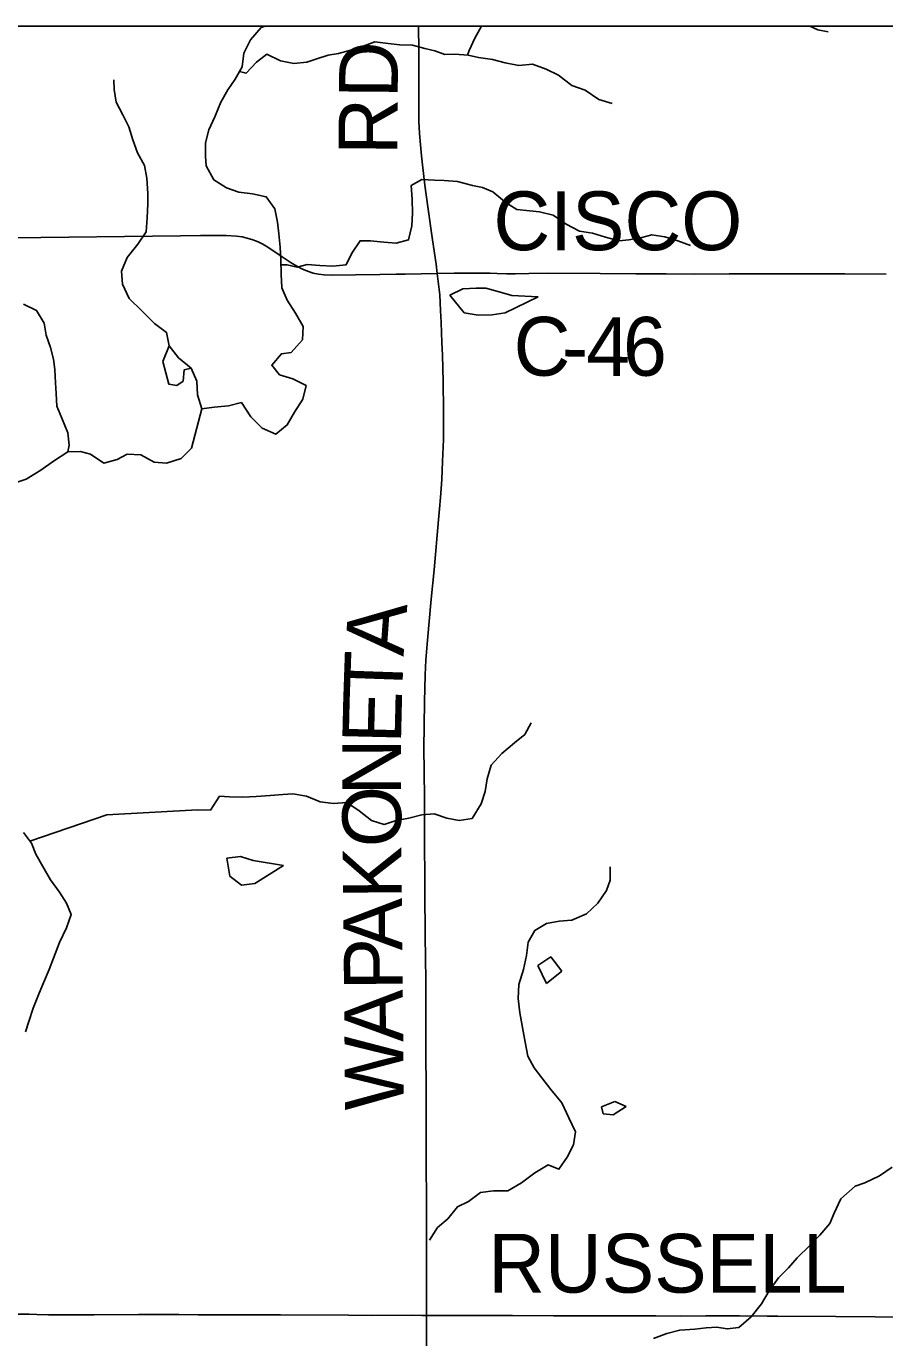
# Model space of a CAD drawing. Extents: x -87 to 2145, y -2128 to 440.
# Drawn here: x 177.65 to 199.56, y -858.65 to -825.19 of the extents above; entities that cross this region are included whole.
import ezdxf

# ---------------------------------------------------------------- set-up
doc = ezdxf.new("R2010")
doc.units = 0
for name, color, linetype in [('GM_X_County_Road', 7, 'Continuous'), ('GM_X_County_Road_Text', 7, 'Continuous'), ('GM_X_Minor_Lake', 7, 'Continuous'), ('GM_X_Minor_River', 7, 'Continuous'), ('GM_X_Township_Road', 7, 'Continuous'), ('SC_Scratch1', 7, 'Continuous')]:
    doc.layers.add(name, color=color, linetype=linetype)

msp = doc.modelspace()

# ---------------------------------------------------------------- linework, layer by layer
at = {"layer": 'GM_X_County_Road'}
for points in [[(188.144, -831.499), (188.12, -831.255), (188.026, -830.639), (187.901, -829.795), (187.826, -829.243), (187.765, -828.722), (187.741, -828.494), (187.714, -828.217), (187.69, -827.924), (187.675, -827.614), (187.673, -827.434), (187.675, -827.106), (187.675, -826.663), (187.675, -826.09), (187.676, -825.664), (187.67, -825.335), (187.668, -825.188)], [(187.869, -858.08), (187.868, -857.384), (187.866, -856.366), (187.867, -855.398), (187.859, -853.971), (187.862, -852.873), (187.859, -852.134), (187.854, -851.527), (187.852, -850.674), (187.85, -849.559), (187.844, -848.935), (187.839, -848.427), (187.83, -847.229), (187.827, -846.786), (187.823, -846.18), (187.819, -845.491), (187.815, -844.9), (187.807, -844.178), (187.805, -843.621), (187.82, -842.424), (187.837, -841.735), (187.854, -841.359), (187.892, -840.853), (187.993, -839.808), (188.062, -839.056), (188.18, -837.782), (188.205, -837.504), (188.228, -837.21), (188.258, -836.751), (188.281, -836.292), (188.301, -835.734), (188.305, -835.307), (188.304, -834.815), (188.296, -834.421), (188.292, -834.257), (188.275, -833.585), (188.264, -833.257), (188.244, -832.75), (188.229, -832.438), (188.206, -832.044), (188.144, -831.499)], [(188.144, -831.499), (188.577, -831.489), (189.495, -831.489), (189.674, -831.496), (189.92, -831.503), (190.051, -831.504), (190.133, -831.502), (190.478, -831.494), (190.953, -831.49), (192.298, -831.495), (193.216, -831.505), (193.987, -831.505), (194.709, -831.51), (195.595, -831.505), (196.07, -831.507), (196.694, -831.506), (197.186, -831.502), (198.548, -831.507), (199.598, -831.511)], [(187.88, -859.664), (187.871, -858.515), (187.869, -858.269), (187.869, -858.08)], [(187.869, -858.08), (188.72, -858.087), (190.065, -858.086), (191.115, -858.089), (191.919, -858.088), (192.526, -858.09), (193.001, -858.091), (193.723, -858.093), (194.362, -858.096), (195.002, -858.092), (195.856, -858.093), (196.561, -858.098), (196.84, -858.1), (198.316, -858.112), (199.316, -858.115), (200.596, -858.128)]]:
    msp.add_lwpolyline(points, dxfattribs=at)
at = {"layer": 'GM_X_Minor_Lake'}
for p, q in [((182.776, -846.417), (182.848, -846.87)), ((190.707, -849.157), (190.93, -849.613)), ((192.965, -852.749), (192.676, -852.623)), ((192.333, -852.756), (192.382, -852.94)), ((192.382, -852.94), (192.63, -852.962))]:
    msp.add_line(p, q, dxfattribs=at)
for points in [[(190.722, -832.091), (190.046, -832.057), (189.727, -831.961), (189.387, -831.873), (189.136, -831.868), (188.795, -831.891), (188.468, -832.046)], [(188.468, -832.046), (188.835, -832.503), (189.185, -832.56), (189.547, -832.548), (189.878, -832.505), (190.722, -832.091)], [(181.141, -833.742), (181.291, -834.317), (181.501, -834.351), (181.663, -834.244), (181.688, -833.953), (181.864, -833.914), (181.543, -833.649), (181.301, -833.342)], [(181.301, -833.342), (181.141, -833.742)], [(184.217, -846.598), (183.447, -846.472), (183.127, -846.375), (182.776, -846.417)], [(182.848, -846.87), (183.145, -847.106), (183.487, -847.063), (184.217, -846.598)], [(191.322, -849.297), (191.042, -848.934), (190.707, -849.157)], [(190.93, -849.613), (191.322, -849.297)], [(192.676, -852.623), (192.333, -852.756)], [(192.63, -852.962), (192.965, -852.749)]]:
    msp.add_lwpolyline(points, dxfattribs=at)
at = {"layer": 'GM_X_Minor_River'}
for points in [[(182.14, -834.948), (182.453, -834.91), (182.815, -834.876), (183.147, -834.791), (183.384, -835.156), (183.672, -835.441), (184.021, -835.597), (184.315, -835.361), (184.5, -835.033), (184.714, -834.706), (184.799, -834.357), (184.46, -834.181), (184.119, -834.085), (183.921, -833.832), (184.166, -833.545), (184.417, -833.509), (184.702, -833.193), (184.726, -832.853), (184.529, -832.509), (184.312, -832.175), (184.175, -831.862), (184.159, -831.511), (184.153, -831.15), (184.137, -830.829), (184.101, -830.488), (184.064, -830.187), (183.998, -829.845), (183.781, -829.541), (183.43, -829.465), (183.079, -829.419), (182.769, -829.314), (182.44, -829.108), (182.244, -828.754), (182.227, -828.504), (182.231, -828.163), (182.315, -827.834), (182.469, -827.496), (182.624, -827.128), (182.799, -826.81), (182.983, -826.543), (183.167, -826.225), (183.211, -825.875), (183.376, -825.537), (183.651, -825.221), (183.749, -825.188)], [(188.914, -825.927), (188.955, -825.809), (189.1, -825.49), (189.27, -825.188)], [(197.649, -825.188), (197.858, -825.283), (198.118, -825.327)], [(183.097, -826.346), (183.266, -826.387), (183.53, -826.101), (183.793, -825.905), (184.143, -826.071), (184.483, -826.136), (184.815, -826.102), (185.067, -826.016), (185.359, -825.93), (185.621, -825.884), (185.873, -825.818), (186.185, -825.723), (186.548, -825.589), (186.889, -825.625), (187.19, -825.66), (187.511, -825.675), (187.831, -825.76), (188.082, -825.814), (188.342, -825.909), (188.593, -825.903), (188.934, -825.928), (189.194, -825.983), (189.555, -826.039), (189.875, -826.124), (190.226, -826.19), (190.578, -826.156), (190.928, -826.281), (191.237, -826.437), (191.575, -826.703), (191.915, -826.818), (192.264, -827.055), (192.604, -827.16)], [(181.301, -833.342), (181.236, -833), (180.93, -832.774), (180.614, -832.457), (180.278, -832.131), (180.114, -831.766), (180.089, -831.435), (180.234, -831.086), (180.499, -830.749), (180.714, -830.431), (180.74, -830.08), (180.755, -829.719), (180.759, -829.458), (180.735, -829.066), (180.67, -828.743), (180.494, -828.419), (180.379, -828.086), (180.274, -827.753), (180.118, -827.449), (179.953, -827.125), (179.898, -826.803), (179.892, -826.552)], [(184.156, -831.28), (184.313, -831.273), (184.573, -831.337), (184.825, -831.271), (185.146, -831.296), (185.477, -831.312), (185.819, -831.277), (185.963, -830.979), (186.177, -830.662), (186.438, -830.666), (186.779, -830.702), (187.1, -830.727), (187.412, -830.642), (187.497, -830.283), (187.511, -829.962), (187.505, -829.602), (187.479, -829.251), (187.752, -829.095), (188.073, -829.12), (188.324, -829.124), (188.665, -829.15), (189.045, -829.256), (189.296, -829.3), (189.566, -829.415), (189.904, -829.691), (190.173, -829.866), (190.504, -829.901), (190.754, -829.925), (191.105, -830.011), (191.433, -830.237), (191.773, -830.413), (192.103, -830.468), (192.434, -830.574), (192.784, -830.66), (193.035, -830.634), (193.367, -830.579), (193.619, -830.513), (193.95, -830.558), (194.28, -830.664), (194.61, -830.779)], [(178.718, -836.051), (178.751, -835.881), (178.716, -835.559), (178.561, -835.185), (178.435, -834.882), (178.42, -834.56), (178.404, -834.289), (178.389, -833.947), (178.353, -833.686), (178.277, -833.383), (178.162, -833.07), (178.116, -832.768), (177.921, -832.443), (177.583, -832.277)], [(182.14, -834.948), (182.024, -834.589), (182.009, -834.248), (181.864, -833.914)], [(178.718, -836.051), (179.039, -836.037), (179.298, -836.111), (179.635, -836.338), (179.977, -836.243), (180.229, -836.106), (180.579, -836.122), (180.917, -836.308), (181.237, -836.334), (181.609, -836.219), (181.873, -835.953), (182.14, -834.948)], [(177.395, -836.833), (177.657, -836.747), (178.031, -836.512), (178.354, -836.286), (178.718, -836.051)], [(182.022, -845.184), (182.354, -845.19), (182.589, -844.833), (182.84, -844.847), (183.181, -844.862), (183.522, -844.838), (183.884, -844.814), (184.206, -844.789), (184.457, -844.773), (184.808, -844.829), (185.157, -844.975), (185.498, -845.02), (185.84, -844.996), (186.149, -845.211), (186.467, -845.457), (186.787, -845.552), (187.1, -845.457), (187.422, -845.392), (187.754, -845.308), (188.065, -845.283), (188.385, -845.398), (188.706, -845.453), (189.038, -845.399), (189.263, -845.032), (189.367, -844.713), (189.421, -844.393), (189.516, -844.044), (189.79, -843.748), (190.115, -843.472), (190.378, -843.256), (190.542, -842.958)], [(182.022, -845.184), (179.71, -845.309), (177.749, -845.978)], [(177.636, -850.844), (177.72, -850.585), (177.835, -850.245), (177.981, -849.856), (178.095, -849.597), (178.24, -849.258), (178.355, -848.969), (178.501, -848.57), (178.687, -848.191), (178.802, -847.852), (178.686, -847.559), (178.5, -847.285), (178.275, -846.97), (178.08, -846.625), (177.904, -846.311), (177.788, -846.028), (177.582, -845.763)], [(187.946, -856.159), (188.151, -855.842), (188.414, -855.616), (188.659, -855.31), (188.942, -855.174), (189.246, -854.949), (189.578, -854.904), (189.949, -854.9), (190.293, -854.695), (190.638, -854.441), (190.971, -854.236), (191.251, -854.35), (191.456, -854.043), (191.62, -853.725), (191.674, -853.396), (191.498, -853.042), (191.322, -852.659), (191.045, -852.314), (190.817, -852.02), (190.619, -851.766), (190.452, -851.463), (190.386, -851.111), (190.32, -850.739), (190.255, -850.358), (190.209, -849.996), (190.223, -849.636), (190.348, -849.257), (190.423, -848.898), (190.467, -848.558), (190.631, -848.26), (190.934, -848.085), (191.256, -848.02), (191.578, -847.995), (191.951, -847.831), (192.246, -847.565), (192.46, -847.238), (192.554, -846.979), (192.558, -846.638)], [(193.659, -858.666), (194.001, -858.541), (194.334, -858.456), (194.716, -858.432), (195.007, -858.397), (195.278, -858.381), (195.539, -858.426), (195.841, -858.391), (196.155, -858.115), (196.42, -857.789), (196.615, -857.452), (196.85, -857.125), (197.104, -856.869), (197.328, -856.612), (197.653, -856.297), (197.907, -856.031), (198.162, -855.735), (198.276, -855.476), (198.441, -855.108), (198.806, -854.784), (199.058, -854.697), (199.432, -854.523), (199.756, -854.298)]]:
    msp.add_lwpolyline(points, dxfattribs=at)
at = {"layer": 'GM_X_Township_Road'}
for points in [[(177.314, -830.586), (181.594, -830.534), (182.102, -830.527), (182.48, -830.524), (182.758, -830.531), (183.02, -830.548), (183.167, -830.565), (183.295, -830.593), (183.436, -830.637), (183.573, -830.69), (183.691, -830.749), (183.818, -830.824), (184.183, -831.075), (184.415, -831.229), (184.557, -831.311), (184.705, -831.384), (184.856, -831.446), (184.981, -831.486), (185.11, -831.513), (185.256, -831.53), (185.453, -831.538), (186.06, -831.533), (186.683, -831.522), (187.093, -831.515), (187.322, -831.513), (187.731, -831.507), (188.144, -831.499)], [(177.271, -858.05), (177.73, -858.053), (177.926, -858.056), (178.221, -858.062), (178.631, -858.066), (179.385, -858.066), (180.517, -858.06), (181.255, -858.06), (181.55, -858.061), (182.042, -858.064), (183.059, -858.063), (184.141, -858.062), (185.88, -858.075), (186.471, -858.079), (187.488, -858.075), (187.75, -858.079), (187.869, -858.08)], [(187.869, -858.08), (188.72, -858.087), (190.065, -858.086), (191.115, -858.089), (191.919, -858.088), (192.526, -858.09), (193.001, -858.091), (193.723, -858.093), (194.362, -858.096), (195.002, -858.092), (195.856, -858.093), (196.561, -858.098), (196.84, -858.1), (198.316, -858.112), (199.316, -858.115), (200.596, -858.128)]]:
    msp.add_lwpolyline(points, dxfattribs=at)
at = {"layer": 'SC_Scratch1'}
msp.add_lwpolyline([(-21.617, -825.188), (230.183, -825.188), (230.183, -1245.188), (-21.617, -1245.188)], close=True, dxfattribs=at)

# ---------------------------------------------------------------- texts
at = {"layer": 'GM_X_County_Road_Text'}
for s, rotation, p in [('RD', 89.5268, (187.123, -828.477)), ('CISCO', 0, (189.578, -830.903)), ('C', 359.598, (190.088, -834.099)), ('4', 359.8637, (191.943, -834.112)), ('6', 0.8685, (192.896, -834.114)), ('-', 359.6626, (191.322, -834.108)), ('A', 85.7522, (187.283, -841.278)), ('T', 88.0025, (187.245, -842.383)), ('E', 88.6241, (187.218, -843.501)), ('N', 89.9781, (187.218, -844.811)), ('O', 90.5355, (187.23, -846.127)), ('K', 90.5464, (187.242, -847.447)), ('A', 90.5464, (187.255, -848.767)), ('P', 90.5464, (187.265, -849.779)), ('A', 90.5464, (187.277, -851.099)), ('W', 90.5478, (187.294, -852.837)), ('RUSSELL', 0, (189.446, -857.5))]:
    msp.add_text(s, height=1.5, rotation=rotation, dxfattribs=at).set_placement(p)

doc.saveas('drawing.dxf')
